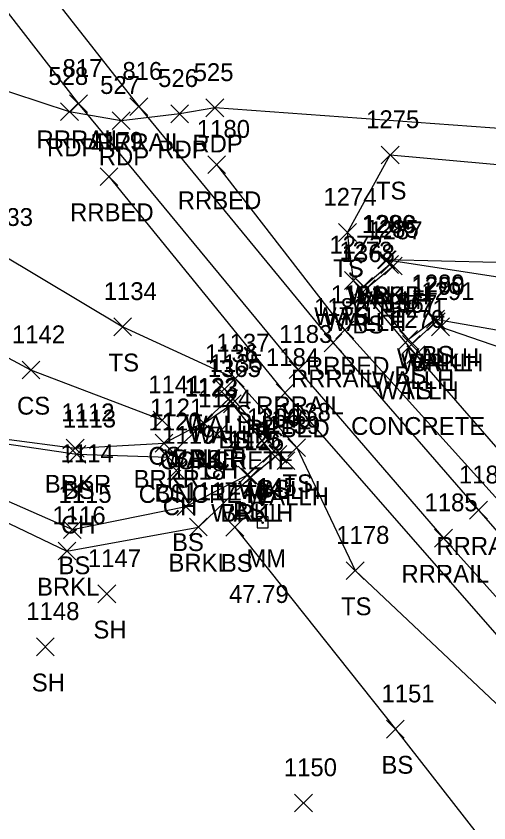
# Model space of a CAD drawing. Extents: x 1679360 to 1685861, y 903420 to 905946.
# Drawn here: x 1679830.3 to 1679883.3, y 903931.8 to 904022.2 of the extents above; entities that cross this region are included whole.
import ezdxf

# ---------------------------------------------------------------- set-up
doc = ezdxf.new("R2010")
doc.units = 0
for name, color, linetype in [('D_A', 7, 'Continuous'), ('D_C', 7, 'Continuous'), ('D_I', 7, 'Continuous'), ('D_TIC', 7, 'Continuous'), ('DHW', 7, 'Continuous'), ('L_A', 7, 'Continuous'), ('L_C', 7, 'Continuous'), ('L_I', 7, 'Continuous'), ('L_TIC', 7, 'Continuous'), ('LAWE', 7, 'Continuous'), ('LELB', 7, 'Continuous'), ('P_A', 7, 'Continuous'), ('P_I', 7, 'Continuous'), ('P_TIC', 7, 'Continuous'), ('PET', 7, 'Continuous'), ('R_A', 7, 'Continuous'), ('R_I', 7, 'Continuous'), ('R_TIC', 7, 'Continuous'), ('RR', 7, 'Continuous'), ('RRB', 7, 'Continuous'), ('S_A', 7, 'Continuous'), ('S_C', 7, 'Continuous'), ('S_I', 7, 'Continuous'), ('SRM', 7, 'Continuous')]:
    doc.layers.add(name, color=color, linetype=linetype)

msp = doc.modelspace()

# ---------------------------------------------------------------- linework, layer by layer
at = {"layer": 'D_TIC'}
for points in [[(1679870.805, 903993.911), (1679872.805, 903995.911)], [(1679872.805, 903993.911), (1679870.805, 903995.911)], [(1679871.169, 903993.361), (1679873.169, 903995.361)], [(1679873.169, 903993.361), (1679871.169, 903995.361)], [(1679867.123, 903991.581), (1679869.123, 903993.581)], [(1679869.123, 903991.581), (1679867.123, 903993.581)], [(1679868.236, 903990.915), (1679870.236, 903992.915)], [(1679870.236, 903990.915), (1679868.236, 903992.915)], [(1679876.394, 903986.966), (1679878.394, 903988.966)], [(1679878.394, 903986.966), (1679876.394, 903988.966)], [(1679876.864, 903986.384), (1679878.864, 903988.384)], [(1679878.864, 903986.384), (1679876.864, 903988.384)], [(1679873.602, 903984.407), (1679875.602, 903986.407)], [(1679875.602, 903984.407), (1679873.602, 903986.407)], [(1679874.104, 903983.265), (1679876.104, 903985.265)], [(1679876.104, 903983.265), (1679874.104, 903985.265)], [(1679852.671, 903979.409), (1679854.671, 903981.409)], [(1679854.671, 903979.409), (1679852.671, 903981.409)], [(1679853.148, 903978.312), (1679855.148, 903980.312)], [(1679855.148, 903978.312), (1679853.148, 903980.312)], [(1679850.31, 903975.645), (1679852.31, 903977.645)], [(1679852.31, 903975.645), (1679850.31, 903977.645)], [(1679858.647, 903972.09), (1679860.647, 903974.09)], [(1679860.647, 903972.09), (1679858.647, 903974.09)], [(1679859.564, 903971.378), (1679861.564, 903973.378)], [(1679861.564, 903971.378), (1679859.564, 903973.378)], [(1679855.581, 903969.528), (1679857.581, 903971.528)], [(1679857.581, 903969.528), (1679855.581, 903971.528)]]:
    msp.add_lwpolyline(points, dxfattribs=at)
at = {"layer": 'DHW'}
for points in [[(1679869.236, 903991.915), (1679872.169, 903994.361), (1679871.805, 903994.911)], [(1679875.104, 903984.265), (1679868.123, 903992.581)], [(1679874.602, 903985.407), (1679877.394, 903987.966), (1679877.864, 903987.384)], [(1679853.671, 903980.409), (1679860.564, 903972.378)], [(1679851.31, 903976.645), (1679854.148, 903979.312)], [(1679856.581, 903970.528), (1679859.647, 903973.09)]]:
    msp.add_lwpolyline(points, dxfattribs=at)
at = {"layer": 'L_TIC'}
for points in [[(1679871.232, 904005.644), (1679873.232, 904007.644)], [(1679873.232, 904005.644), (1679871.232, 904007.644)], [(1679866.449, 903996.953), (1679868.449, 903998.953)], [(1679868.449, 903996.953), (1679866.449, 903998.953)], [(1679870.805, 903993.911), (1679872.805, 903995.911)], [(1679872.805, 903993.911), (1679870.805, 903995.911)], [(1679870.887, 903993.882), (1679872.887, 903995.882)], [(1679872.887, 903993.882), (1679870.887, 903995.882)], [(1679871.593, 903993.19), (1679873.593, 903995.19)], [(1679873.593, 903993.19), (1679871.593, 903995.19)], [(1679871.593, 903993.19), (1679873.593, 903995.19)], [(1679873.593, 903993.19), (1679871.593, 903995.19)], [(1679867.123, 903991.581), (1679869.123, 903993.581)], [(1679869.123, 903991.581), (1679867.123, 903993.581)], [(1679868.541, 903990.636), (1679870.541, 903992.636)], [(1679870.541, 903990.636), (1679868.541, 903992.636)], [(1679868.541, 903990.636), (1679870.541, 903992.636)], [(1679870.541, 903990.636), (1679868.541, 903992.636)], [(1679876.317, 903987.235), (1679878.317, 903989.235)], [(1679878.317, 903987.235), (1679876.317, 903989.235)], [(1679876.317, 903987.235), (1679878.317, 903989.235)], [(1679878.317, 903987.235), (1679876.317, 903989.235)], [(1679841.28, 903986.378), (1679843.28, 903988.378)], [(1679843.28, 903986.378), (1679841.28, 903988.378)], [(1679876.864, 903986.384), (1679878.864, 903988.384)], [(1679878.864, 903986.384), (1679876.864, 903988.384)], [(1679873.277, 903984.96), (1679875.277, 903986.96)], [(1679875.277, 903984.96), (1679873.277, 903986.96)], [(1679874.104, 903983.265), (1679876.104, 903985.265)], [(1679876.104, 903983.265), (1679874.104, 903985.265)], [(1679831.005, 903981.539), (1679833.005, 903983.539)], [(1679833.005, 903981.539), (1679831.005, 903983.539)], [(1679853.89, 903980.602), (1679855.89, 903982.602)], [(1679855.89, 903980.602), (1679853.89, 903982.602)], [(1679853.549, 903977.756), (1679855.549, 903979.756)], [(1679855.549, 903977.756), (1679853.549, 903979.756)], [(1679845.701, 903975.921), (1679847.701, 903977.921)], [(1679847.701, 903975.921), (1679845.701, 903977.921)], [(1679850.31, 903975.645), (1679852.31, 903977.645)], [(1679852.31, 903975.645), (1679850.31, 903977.645)], [(1679850.382, 903975.558), (1679852.382, 903977.558)], [(1679852.382, 903975.558), (1679850.382, 903977.558)], [(1679850.382, 903975.558), (1679852.382, 903977.558)], [(1679852.382, 903975.558), (1679850.382, 903977.558)], [(1679851.863, 903974.35), (1679853.863, 903976.35)], [(1679853.863, 903974.35), (1679851.863, 903976.35)], [(1679845.91, 903973.341), (1679847.91, 903975.341)], [(1679847.91, 903973.341), (1679845.91, 903975.341)], [(1679835.965, 903972.787), (1679837.965, 903974.787)], [(1679837.965, 903972.787), (1679835.965, 903974.787)], [(1679857.992, 903972.228), (1679859.992, 903974.228)], [(1679859.992, 903972.228), (1679857.992, 903974.228)], [(1679857.992, 903972.228), (1679859.992, 903974.228)], [(1679859.992, 903972.228), (1679857.992, 903974.228)], [(1679860.766, 903972.84), (1679862.766, 903974.84)], [(1679862.766, 903972.84), (1679860.766, 903974.84)], [(1679836.139, 903972.094), (1679838.139, 903974.094)], [(1679838.139, 903972.094), (1679836.139, 903974.094)], [(1679846.38, 903971.765), (1679848.38, 903973.765)], [(1679848.38, 903971.765), (1679846.38, 903973.765)], [(1679847.278, 903970.27), (1679849.278, 903972.27)], [(1679849.278, 903970.27), (1679847.278, 903972.27)], [(1679855.205, 903969.751), (1679857.205, 903971.751)], [(1679857.205, 903969.751), (1679855.205, 903971.751)], [(1679855.205, 903969.751), (1679857.205, 903971.751)], [(1679857.205, 903969.751), (1679855.205, 903971.751)], [(1679855.581, 903969.528), (1679857.581, 903971.528)], [(1679857.581, 903969.528), (1679855.581, 903971.528)], [(1679835.875, 903968.206), (1679837.875, 903970.206)], [(1679837.875, 903968.206), (1679835.875, 903970.206)], [(1679848.36, 903966.246), (1679850.36, 903968.246)], [(1679850.36, 903966.246), (1679848.36, 903968.246)], [(1679835.645, 903963.65), (1679837.645, 903965.65)], [(1679837.645, 903963.65), (1679835.645, 903965.65)], [(1679849.756, 903963.941), (1679851.756, 903965.941)], [(1679851.756, 903963.941), (1679849.756, 903965.941)], [(1679853.827, 903963.919), (1679855.827, 903965.919)], [(1679855.827, 903963.919), (1679853.827, 903965.919)], [(1679835.034, 903961.252), (1679837.034, 903963.252)], [(1679837.034, 903961.252), (1679835.034, 903963.252)], [(1679867.316, 903959.054), (1679869.316, 903961.054)], [(1679869.316, 903959.054), (1679867.316, 903961.054)], [(1679867.316, 903959.054), (1679869.316, 903961.054)], [(1679869.316, 903959.054), (1679867.316, 903961.054)], [(1679839.509, 903956.447), (1679841.509, 903958.447)], [(1679841.509, 903956.447), (1679839.509, 903958.447)], [(1679832.611, 903950.515), (1679834.611, 903952.515)], [(1679834.611, 903950.515), (1679832.611, 903952.515)], [(1679871.814, 903941.29), (1679873.814, 903943.29)], [(1679873.814, 903941.29), (1679871.814, 903943.29)], [(1679861.535, 903933.015), (1679863.535, 903935.015)], [(1679863.535, 903933.015), (1679861.535, 903935.015)]]:
    msp.add_lwpolyline(points, dxfattribs=at)
at = {"layer": 'LAWE'}
for points in [[(1679770.758, 904003.113), (1679774.622, 904001.969), (1679779.149, 903998.281), (1679800.693, 903989.211), (1679821, 903975.857), (1679836.965, 903973.787), (1679846.91, 903974.341), (1679851.31, 903976.645)], [(1679754.084, 903995.867), (1679760.871, 903994.62), (1679770.523, 903990.096), (1679818.461, 903970.652), (1679836.034, 903962.252), (1679850.756, 903964.941), (1679856.581, 903970.528)], [(1679871.805, 903994.911), (1679890.312, 903994.48), (1679904.668, 903985.721), (1679929.473, 903971.44), (1679948.499, 903963.819), (1679973.974, 903954.719)], [(1679877.864, 903987.384), (1679888.185, 903983.814), (1679901.387, 903977.613), (1679926.813, 903963.593), (1679943.836, 903957.668), (1679971.853, 903947.012)]]:
    msp.add_lwpolyline(points, dxfattribs=at)
at = {"layer": 'LELB'}
for points in [[(1679826.909, 903946.775), (1679816.139, 903962.498), (1679799.3, 903967.949), (1679786.9, 903972.592), (1679770.418, 903982.075), (1679752.253, 903992.328), (1679749.667, 904002.531), (1679749.546, 904012.229), (1679768.469, 904013.239), (1679790.366, 904010.321), (1679808.954, 904003.393), (1679828.407, 903995.686), (1679842.28, 903987.378), (1679854.89, 903981.602), (1679861.766, 903973.84), (1679868.316, 903960.054)], [(1679868.123, 903992.581), (1679867.449, 903997.953), (1679872.232, 904006.644), (1679908.317, 904003.394), (1679946.047, 904001.015), (1679984.241, 903997.59), (1680029.094, 903994.379), (1680069.55, 903991.418), (1680115.048, 903987.488), (1680162.583, 903984.342), (1680207.954, 903980.989)], [(1679753.265, 903993.087), (1679754.084, 903995.867), (1679755.517, 904001.673), (1679758.772, 904003.433), (1679764.509, 904003.328), (1679769.411, 904003.26), (1679777.875, 903996.933), (1679798.619, 903986.362), (1679820.173, 903975.618), (1679837.139, 903973.094), (1679847.38, 903972.765), (1679851.382, 903976.558)], [(1679846.701, 903976.921), (1679832.005, 903982.539), (1679812.152, 903993.161), (1679777.904, 904003.912)], [(1679755.517, 904001.673), (1679762.265, 903996.209), (1679771.871, 903991.159), (1679797.314, 903982.397), (1679818.901, 903972.468), (1679836.645, 903964.65), (1679849.36, 903967.246), (1679856.205, 903970.751)], [(1679872.593, 903994.19), (1679869.541, 903991.636)], [(1679872.593, 903994.19), (1679871.887, 903994.882), (1679890.104, 903992.101), (1679903.013, 903981.546), (1679927.794, 903968.15), (1679945.991, 903961.002), (1679973.216, 903951.744)], [(1679877.317, 903988.235), (1679874.277, 903985.96), (1679869.541, 903991.636)], [(1679877.317, 903988.235), (1679889.488, 903986.11), (1679902.1, 903979.853), (1679927.266, 903966.366), (1679945.306, 903959.401), (1679972.678, 903949.632)], [(1680042.476, 903807.682), (1680020.066, 903831.145), (1679994.569, 903854.854), (1679973.518, 903877.192), (1679947.493, 903902.981), (1679918.081, 903936.814), (1679895.506, 903960.774), (1679875.104, 903984.265)], [(1679851.382, 903976.558), (1679854.549, 903978.756), (1679858.992, 903973.228)], [(1679856.205, 903970.751), (1679858.992, 903973.228)], [(1679854.827, 903964.919), (1679872.814, 903942.29), (1679891.125, 903918.818), (1679918.926, 903890.388), (1679939.756, 903869.145), (1679968.6, 903838.005), (1679992.841, 903818.007), (1680020.69, 903787.695)], [(1680027.001, 903796.796), (1680001.4, 903822.237), (1679984.382, 903839.7), (1679957.185, 903867.741), (1679928.197, 903894.121), (1679909.106, 903915.884), (1679887.98, 903941.486), (1679868.316, 903960.054)]]:
    msp.add_lwpolyline(points, dxfattribs=at)
at = {"layer": 'P_TIC'}
for points in [[(1679835.311, 904010.491), (1679837.311, 904012.491)], [(1679837.311, 904010.491), (1679835.311, 904012.491)], [(1679847.664, 904010.26), (1679849.664, 904012.26)], [(1679849.664, 904010.26), (1679847.664, 904012.26)], [(1679851.589, 904010.923), (1679853.589, 904012.923)], [(1679853.589, 904010.923), (1679851.589, 904012.923)], [(1679841.11, 904009.48), (1679843.11, 904011.48)], [(1679843.11, 904009.48), (1679841.11, 904011.48)]]:
    msp.add_lwpolyline(points, dxfattribs=at)
at = {"layer": 'PET'}
msp.add_lwpolyline([(1680207.925, 903985.129), (1680151.693, 903989.51), (1680097.956, 903992.814), (1680047.952, 903996.664), (1679996.841, 904001.699), (1679939.177, 904006.29), (1679891.591, 904009.092), (1679852.589, 904011.923), (1679848.664, 904011.26), (1679842.11, 904010.48), (1679836.311, 904011.491), (1679826.762, 904014.608), (1679807.928, 904016.053), (1679789.628, 904016.53)], dxfattribs=at)
at = {"layer": 'R_TIC'}
for points in [[(1679836.335, 904011.385), (1679838.335, 904013.385)], [(1679838.335, 904011.385), (1679836.335, 904013.385)], [(1679843.096, 904011.062), (1679845.096, 904013.062)], [(1679845.096, 904011.062), (1679843.096, 904013.062)], [(1679851.795, 904004.562), (1679853.795, 904006.562)], [(1679853.795, 904004.562), (1679851.795, 904006.562)], [(1679839.738, 904003.217), (1679841.738, 904005.217)], [(1679841.738, 904003.217), (1679839.738, 904005.217)], [(1679866.147, 903986.017), (1679868.147, 903988.017)], [(1679868.147, 903986.017), (1679866.147, 903988.017)], [(1679864.832, 903984.593), (1679866.832, 903986.593)], [(1679866.832, 903984.593), (1679864.832, 903986.593)], [(1679860.93, 903981.575), (1679862.93, 903983.575)], [(1679862.93, 903981.575), (1679860.93, 903983.575)], [(1679859.452, 903978.987), (1679861.452, 903980.987)], [(1679861.452, 903978.987), (1679859.452, 903980.987)], [(1679881.113, 903965.823), (1679883.113, 903967.823)], [(1679883.113, 903965.823), (1679881.113, 903967.823)], [(1679877.201, 903962.702), (1679879.201, 903964.702)], [(1679879.201, 903962.702), (1679877.201, 903964.702)]]:
    msp.add_lwpolyline(points, dxfattribs=at)
at = {"layer": 'RR'}
for points in [[(1679824.636, 904028.723), (1679837.335, 904012.385), (1679861.93, 903982.575), (1679878.201, 903963.702), (1679892.43, 903947.813), (1679907.949, 903930.191), (1679922.381, 903914.406), (1679937.847, 903897.677), (1679952.054, 903882.523), (1679968.97, 903864.985), (1679984.514, 903848.778), (1680002.835, 903830.071), (1680018.619, 903814.033), (1680033.052, 903799.461), (1680047.501, 903784.671), (1680062.832, 903769.48), (1680079.575, 903752.46), (1680095.318, 903736.478)], [(1679831.29, 904028.454), (1679844.096, 904012.062), (1679865.832, 903985.593), (1679882.113, 903966.823), (1679896.054, 903950.914), (1679911.539, 903933.695), (1679925.868, 903917.928), (1679941.581, 903900.906), (1679955.487, 903886.236), (1679972.276, 903868.599), (1679988.045, 903852.199), (1680006.222, 903833.297), (1680022.216, 903817.371), (1680036.492, 903802.967), (1680051.111, 903788.214), (1680066.385, 903772.907), (1680082.823, 903756.115), (1680099.284, 903739.482)]]:
    msp.add_lwpolyline(points, dxfattribs=at)
at = {"layer": 'RRB'}
for points in [[(1679852.795, 904005.562), (1679867.147, 903987.017), (1679898.433, 903952.3), (1679928.167, 903919.501), (1679957.856, 903886.729), (1679990.498, 903854.155), (1680024.928, 903818.736), (1680038.518, 903804.879)], [(1679840.738, 904004.217), (1679860.452, 903979.987), (1679889.935, 903946.255), (1679920.699, 903912.732), (1679950.152, 903880.788), (1679982.316, 903846.881), (1680017.14, 903812.199), (1680030.44, 903798.069)]]:
    msp.add_lwpolyline(points, dxfattribs=at)
at = {"layer": 'SRM'}
for p, q in [((1679858.586, 903966.089), (1679857.336, 903966.089)), ((1679857.336, 903966.089), (1679857.336, 903964.839)), ((1679858.586, 903966.089), (1679857.336, 903966.089)), ((1679857.336, 903966.089), (1679857.336, 903964.839)), ((1679858.586, 903964.839), (1679858.586, 903966.089)), ((1679858.586, 903964.839), (1679858.586, 903966.089)), ((1679857.336, 903964.839), (1679858.586, 903964.839)), ((1679857.336, 903964.839), (1679858.586, 903964.839))]:
    msp.add_line(p, q, dxfattribs=at)
msp.add_circle((1679857.937, 903965.427), 0.0833, dxfattribs=at)

# ---------------------------------------------------------------- texts
at = {"layer": 'D_A'}
for p in [(1679867.396, 903989.911), (1679867.76, 903989.361), (1679863.713, 903987.581), (1679864.827, 903986.915), (1679872.985, 903982.966), (1679873.455, 903982.384), (1679870.193, 903980.407), (1679870.694, 903979.265), (1679849.261, 903975.409), (1679849.738, 903974.312), (1679846.9, 903971.645), (1679855.237, 903968.09), (1679856.155, 903967.378), (1679852.172, 903965.528)]:
    msp.add_text('WALLH', height=2, dxfattribs=at).set_placement(p)
at = {"layer": 'D_C'}
for p in [(1679867.86, 903975.265), (1679846.427, 903971.409)]:
    msp.add_text('CONCRETE', height=2, dxfattribs=at).set_placement(p)
at = {"layer": 'D_I'}
for s, p in [('1286', (1679869.057, 903997.911)), ('1285', (1679869.476, 903997.361)), ('1272', (1679865.43, 903995.581)), ('1273', (1679866.543, 903994.915)), ('1290', (1679874.614, 903990.966)), ('1291', (1679875.738, 903990.384)), ('1271', (1679872.476, 903988.407)), ('1270', (1679872.324, 903987.265)), ('1136', (1679851.49, 903983.409)), ('1135', (1679852.022, 903982.312)), ('1122', (1679849.184, 903979.645)), ('1140', (1679857.434, 903976.09)), ('1139', (1679858.43, 903975.378)), ('1126', (1679854.4, 903973.528))]:
    msp.add_text(s, height=2, dxfattribs=at).set_placement(p)
at = {"layer": 'L_A'}
for s, p in [('TS', (1679870.641, 904001.644)), ('TS', (1679865.859, 903992.953)), ('BRKR', (1679868.396, 903989.911)), ('BS', (1679870.328, 903989.882)), ('BS', (1679871.034, 903989.19)), ('BS', (1679871.034, 903989.19)), ('TS', (1679866.532, 903987.581)), ('BS', (1679867.982, 903986.636)), ('BS', (1679867.982, 903986.636)), ('BS', (1679875.758, 903983.235)), ('BS', (1679875.758, 903983.235)), ('TS', (1679840.69, 903982.378)), ('BRKL', (1679874.51, 903982.384)), ('BS', (1679872.718, 903980.96)), ('TS', (1679873.513, 903979.265)), ('CS', (1679830.445, 903977.539)), ('TS', (1679853.3, 903976.602)), ('BS', (1679852.99, 903973.756)), ('CS', (1679845.142, 903971.921)), ('BRKR', (1679847.9, 903971.645)), ('BS', (1679849.823, 903971.558)), ('BS', (1679849.823, 903971.558)), ('CH', (1679851.351, 903970.35)), ('BRKR', (1679833.556, 903968.787)), ('BRKR', (1679843.5, 903969.341)), ('TS', (1679860.176, 903968.84)), ('BS', (1679835.58, 903968.094)), ('BS', (1679845.821, 903967.765)), ('BS', (1679857.433, 903968.228)), ('BS', (1679857.433, 903968.228)), ('CH', (1679846.767, 903966.27)), ('BRKL', (1679853.227, 903965.528)), ('BS', (1679854.646, 903965.751)), ('BS', (1679854.646, 903965.751)), ('CH', (1679835.364, 903964.206)), ('BS', (1679847.801, 903962.246)), ('BS', (1679835.086, 903959.65)), ('BRKL', (1679847.402, 903959.941)), ('BS', (1679853.267, 903959.919)), ('BRKL', (1679832.68, 903957.252)), ('TS', (1679866.725, 903955.054)), ('TS', (1679866.725, 903955.054)), ('SH', (1679838.997, 903952.447)), ('SH', (1679832.099, 903946.515)), ('BS', (1679871.255, 903937.29))]:
    msp.add_text(s, height=2, dxfattribs=at).set_placement(p)
at = {"layer": 'L_C'}
msp.add_text('CONCRETE', height=2, dxfattribs=at).set_placement((1679844.066, 903967.645))
at = {"layer": 'L_I'}
for s, p in [('1275', (1679869.539, 904009.644)), ('1274', (1679864.756, 904000.953)), ('1133', (1679826.281, 903998.686)), ('1286', (1679869.057, 903997.911)), ('1288', (1679869.194, 903997.882)), ('1287', (1679869.9, 903997.19)), ('1287', (1679869.9, 903997.19)), ('1272', (1679865.43, 903995.581)), ('1368', (1679866.801, 903994.636)), ('1368', (1679866.801, 903994.636)), ('1289', (1679874.616, 903991.235)), ('1289', (1679874.616, 903991.235)), ('1134', (1679840.154, 903990.378)), ('1291', (1679875.738, 903990.384)), ('1367', (1679871.536, 903988.96)), ('1270', (1679872.324, 903987.265)), ('1142', (1679829.879, 903985.539)), ('1137', (1679852.764, 903984.602)), ('1365', (1679851.809, 903981.756)), ('1141', (1679845.142, 903979.921)), ('1122', (1679849.184, 903979.645)), ('1123', (1679849.256, 903979.558)), ('1123', (1679849.256, 903979.558)), ('1124', (1679850.737, 903978.35)), ('1112', (1679835.406, 903976.787)), ('1121', (1679845.35, 903977.341)), ('1138', (1679859.64, 903976.84)), ('1113', (1679835.58, 903976.094)), ('1366', (1679856.197, 903976.228)), ('1366', (1679856.197, 903976.228)), ('1120', (1679845.167, 903975.765)), ('1119', (1679846.711, 903974.27)), ('1125', (1679854.079, 903973.751)), ('1125', (1679854.079, 903973.751)), ('1126', (1679854.4, 903973.528)), ('1114', (1679835.316, 903972.206)), ('1118', (1679847.801, 903970.246)), ('1117', (1679849.197, 903967.941)), ('1146', (1679852.645, 903967.919)), ('1115', (1679835.086, 903967.65)), ('1116', (1679834.42, 903965.252)), ('1178', (1679866.19, 903963.054)), ('1178', (1679866.19, 903963.054)), ('1147', (1679838.383, 903960.447)), ('1148', (1679831.485, 903954.515)), ('1151', (1679871.255, 903945.29)), ('1150', (1679860.323, 903937.015))]:
    msp.add_text(s, height=2, dxfattribs=at).set_placement(p)
at = {"layer": 'P_A'}
for p in [(1679850.077, 904006.923), (1679833.799, 904006.491), (1679846.152, 904006.26), (1679839.598, 904005.48)]:
    msp.add_text('RDP', height=2, dxfattribs=at).set_placement(p)
at = {"layer": 'P_I'}
for s, p in [('525', (1679850.227, 904014.923)), ('528', (1679833.949, 904014.491)), ('526', (1679846.246, 904014.26)), ('527', (1679839.747, 904013.48))]:
    msp.add_text(s, height=2, dxfattribs=at).set_placement(p)
at = {"layer": 'R_A'}
for s, p in [('RRRAIL', (1679832.626, 904007.385)), ('RRRAIL', (1679839.387, 904007.062)), ('RRBED', (1679848.441, 904000.562)), ('RRBED', (1679836.384, 903999.217)), ('RRBED', (1679862.793, 903982.017)), ('RRRAIL', (1679861.123, 903980.593)), ('RRRAIL', (1679857.221, 903977.575)), ('RRBED', (1679856.098, 903974.987)), ('RRRAIL', (1679877.405, 903961.823)), ('RRRAIL', (1679873.492, 903958.702))]:
    msp.add_text(s, height=2, dxfattribs=at).set_placement(p)
at = {"layer": 'R_I'}
for s, p in [('817', (1679835.54, 904015.385)), ('816', (1679842.245, 904015.062)), ('1180', (1679850.583, 904008.562)), ('1179', (1679838.605, 904007.217)), ('1181', (1679865.588, 903990.017)), ('1182', (1679863.706, 903988.593)), ('1183', (1679859.804, 903985.575)), ('1184', (1679858.326, 903982.987)), ('1186', (1679879.932, 903969.823)), ('1185', (1679876.075, 903966.702))]:
    msp.add_text(s, height=2, dxfattribs=at).set_placement(p)
at = {"layer": 'S_A'}
msp.add_text('MM', height=2, dxfattribs=at).set_placement((1679856.124, 903960.432))
at = {"layer": 'S_C'}
msp.add_text('47.79', height=2, dxfattribs=at).set_placement((1679854.179, 903956.432))
at = {"layer": 'S_I'}
msp.add_text('1145', height=2, dxfattribs=at).set_placement((1679855.809, 903968.432))

doc.saveas('drawing.dxf')
